(* Logix 5000 project; controller SMD34E2_EDS_AOI_Sample_RSLogix_V31 vendor 1 type 14 code 92 rev 31.11; software revision 31.00 *)

TASK MainTask (continuous, watchdog 500 ms) : MainProgram
TASK SMD34E2_follower_circular (task) : SMD34E2_follower_circular

MODULES
   Local : vendor 1 type 14 code 92 (ICP 0, rev 31.11)
      EN2TR : vendor 1 type 12 code 200 (ICP 2, Ethernet 192.168.0.5, rev 10.1)
         AMCI_SMD34E2 : vendor 10 type 12 code 28 (Ethernet 192.168.0.50, rev 1.6, StandardDataDriven RPI 8 ms)
END_MODULES

ADD_ON_INSTRUCTION AMCI_SMD34E2_Absolute_Move   (* revision 5.0, vendor AMCI, ExecuteEnableInFalse *)
// Revision note:
// Version 5.0 added the (hidden) ability to program the motor current and unlatched the error bit if the rung goes false.
VAR_INPUT
   Axis_Status_Bits : INT; {required}
   Type_0_for_standard_1_for_indexed : BOOL;
   Target_Position : DINT; {required}
   Programmed_Speed : DINT; {required}
   Acceleration : INT; {required}
   Deceleration : INT; {required}
   motor_current : INT;
   Jerk : INT;
END_VAR
VAR_IN_OUT
   AMCI_SMD34E2_output_data : _000A:SMD34E2_788832CB:O:0; {required}
END_VAR
VAR_OUTPUT
   EN : BOOL; {access Read Only, visible}
   ER : BOOL; {access Read Only, visible}
END_VAR
VAR
   Upper_Result_X_1000 : DINT;
   command_data_block : INT[10];
        [1]   // Command Bits LSW
        [3]   // Lower Target Position
        [0]   // Command Bits MSW
        [5]   // Lower Programmed Speed
        [2]   // Upper Target Position
        [4]   // Upper Programmed Speed
END_VAR

ROUTINE EnableInFalse   (* ladder *)
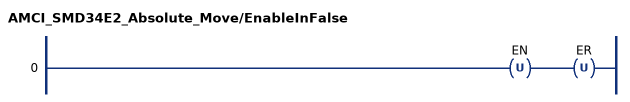
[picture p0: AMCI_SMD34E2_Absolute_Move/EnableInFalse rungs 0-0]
   0: OTU(EN)OTU(ER);
END_ROUTINE

ROUTINE Logic   (* ladder *)
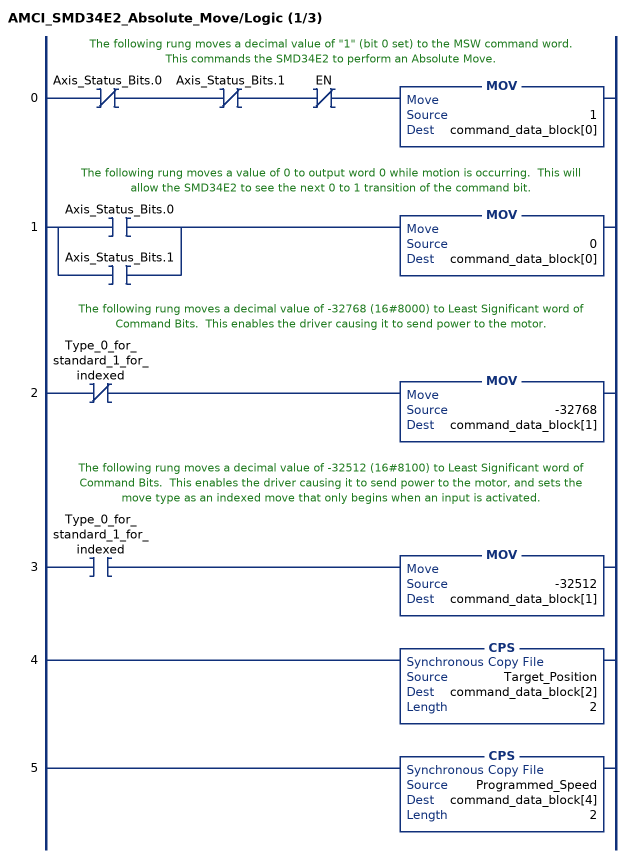
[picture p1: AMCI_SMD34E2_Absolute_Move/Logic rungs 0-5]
   // The following rung moves a decimal value of "1" (bit 0 set) to the MSW command word.  This commands the SMD34E2 to perform an Absolute Move.
   0: XIO(Axis_Status_Bits.0)XIO(Axis_Status_Bits.1)XIO(EN)MOV(1,command_data_block[0]);
   // The following rung moves a value of 0 to output word 0 while motion is occurring.  This will allow the SMD34E2 to see the next 0 to 1 transition of the command bit.
   1: [XIC(Axis_Status_Bits.0) ,XIC(Axis_Status_Bits.1) ]MOV(0,command_data_block[0]);
   // The following rung moves a decimal value of -32768 (16#8000) to Least Significant word of Command Bits.  This enables the driver causing it to send power to the motor.
   2: XIO(Type_0_for_standard_1_for_indexed)MOV(-32768,command_data_block[1]);
   // The following rung moves a decimal value of -32512 (16#8100) to Least Significant word of Command Bits.  This enables the driver causing it to send power to the motor, and sets the move type as an indexed move that only begins when an input is activated.
   3: XIC(Type_0_for_standard_1_for_indexed)MOV(-32512,command_data_block[1]);
   4: CPS(Target_Position,command_data_block[2],2);
   5: CPS(Programmed_Speed,command_data_block[4],2);
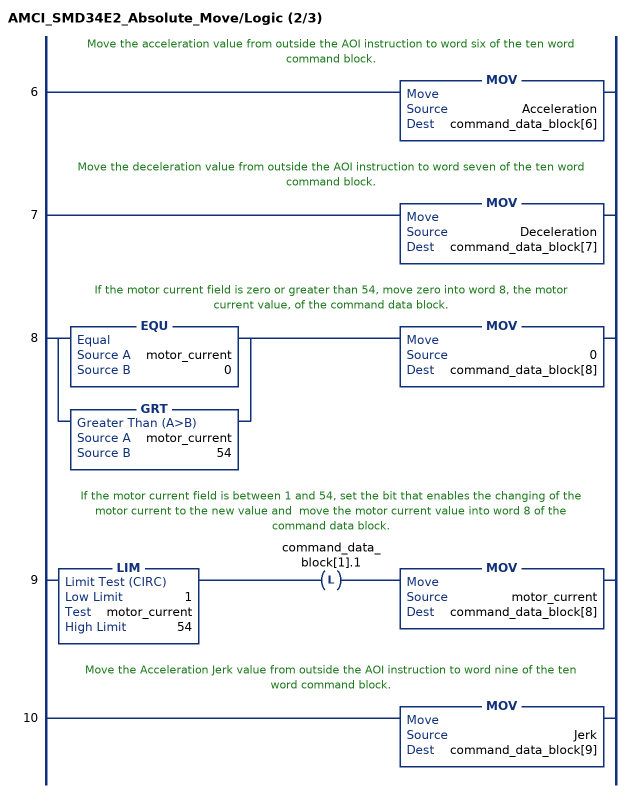
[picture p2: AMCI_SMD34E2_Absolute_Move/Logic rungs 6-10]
   // Move the acceleration value from outside the AOI instruction to word six of the ten word command block.
   6: MOV(Acceleration,command_data_block[6]);
   // Move the deceleration value from outside the AOI instruction to word seven of the ten word command block.
   7: MOV(Deceleration,command_data_block[7]);
   // If the motor current field is zero or greater than 54, move zero into word 8, the motor current value, of the command data block.
   8: [EQU(motor_current,0) ,GRT(motor_current,54) ]MOV(0,command_data_block[8]);
   // If the motor current field is between 1 and 54, set the bit that enables the changing of the motor current to the new value and  move the motor current value into word 8 of the command data block.
   9: LIM(1,motor_current,54)OTL(command_data_block[1].1)MOV(motor_current,command_data_block[8]);
   // Move the Acceleration Jerk value from outside the AOI instruction to word nine of the ten word command block.
   10: MOV(Jerk,command_data_block[9]);
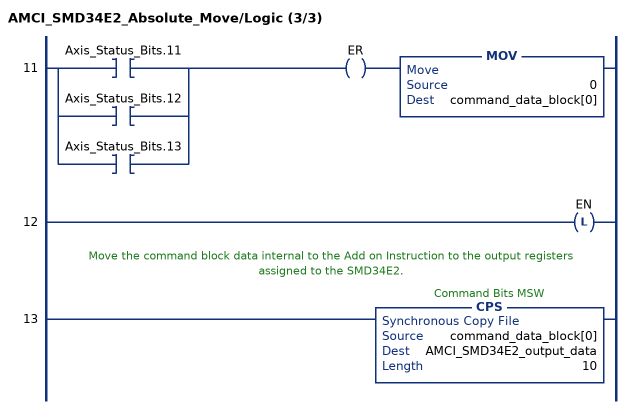
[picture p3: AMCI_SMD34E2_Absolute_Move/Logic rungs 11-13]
   11: [XIC(Axis_Status_Bits.11) ,XIC(Axis_Status_Bits.12) ,XIC(Axis_Status_Bits.13) ]OTE(ER)MOV(0,command_data_block[0]);
   12: OTL(EN);
   // Move the command block data internal to the Add on Instruction to the output registers assigned to the SMD34E2.
   13: CPS(command_data_block[0],AMCI_SMD34E2_output_data,10);
END_ROUTINE
END_ADD_ON_INSTRUCTION

ADD_ON_INSTRUCTION AMCI_SMD34E2_Axis_Follower_Circular   (* revision 5.0, vendor AMCI, ExecuteEnableInFalse *)
// Revision note:
// Version 5.0  unlatches the error bit if the rung goes false.  Also modified the Axis Follower commands to by default use the jog CCW command and have an option of the jog CW command.  (The status bits of the jog CCW update faster and the jog CW has smoother motion.)
// Help:
// 2/2017: V0 is the initial release
// 7/2017: V1 added enable and error bits.
// 5/2019: V2 added unlatching the error bit when the rung goes false and the ability to select between normal (jog CCW) and continuous follower (jog CW)
VAR_OUTPUT
   EN : BOOL; {visible}
END_VAR
VAR_INPUT
   Axis_Status_Bits : INT; {required}
   _0_for_Normal_1_for_Continuous : BOOL;
   _0_follow_motor_1_follow_encoder : BOOL;
   Follower_Position : REAL; {required}
   Follower_Velocity : REAL; {required}
   Acceleration : INT; {required}
   Deceleration : INT; {required}
   Proportional_Coefficient : INT; {required}
   Conversion_Constant : REAL; {required}
   Position_Unwind : INT; {required}
END_VAR
VAR_OUTPUT
   Axis_Follower_occurring : BOOL; {visible}
END_VAR
VAR_IN_OUT
   AMCI_SMD34E2_output_data : _000A:SMD34E2_788832CB:O:0; {required}
END_VAR
VAR_OUTPUT
   ER : BOOL; {visible}
END_VAR
VAR
   command_data_block : INT[10];
        [1]   // Command Bits LSW
        [3]   // Lower Target Position
        [5]   // Lower Programmed Speed
        [0]   // Command Bits MSW
        [2]   // Upper Target Position
        [4]   // Upper Programmed Speed
   axis_follower_position : DINT;
   axis_follower_velocity : DINT;
END_VAR

ROUTINE EnableInFalse   (* ladder *)
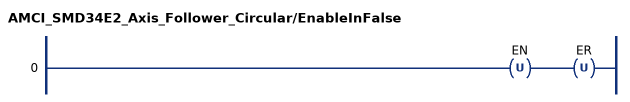
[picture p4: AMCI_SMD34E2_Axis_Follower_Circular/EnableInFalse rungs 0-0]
   0: OTU(EN)OTU(ER);
END_ROUTINE

ROUTINE Logic   (* ladder *)
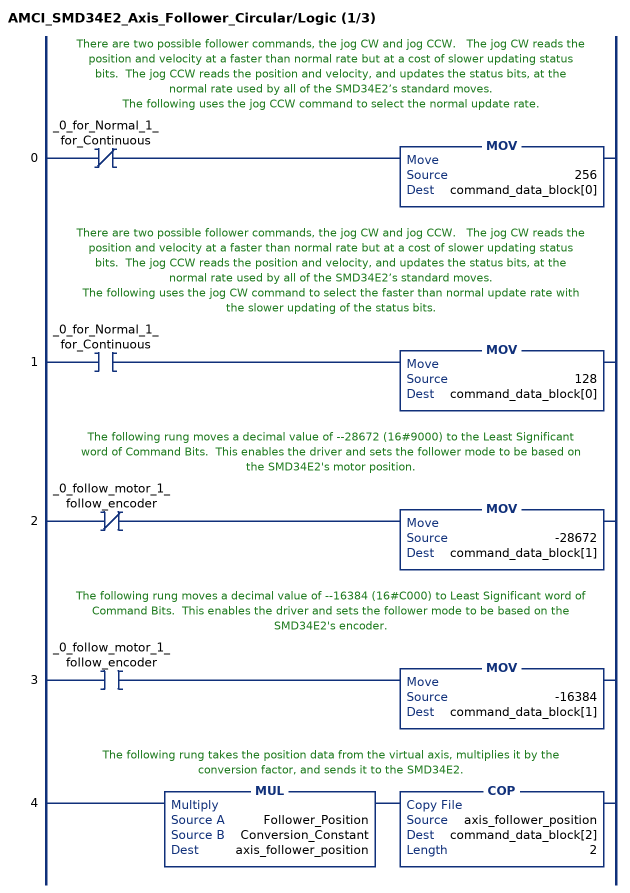
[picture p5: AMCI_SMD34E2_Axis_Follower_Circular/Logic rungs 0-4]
   // There are two possible follower commands, the jog CW and jog CCW.   The jog CW reads the position and velocity at a faster than normal rate but at a cost of slower updating status bits.  The jog CCW reads the position and velocity, and updates the status bits, at the normal rate used by all of the SMD34E2’s standard moves.
   // The following uses the jog CCW command to select the normal update rate.
   0: XIO(_0_for_Normal_1_for_Continuous)MOV(256,command_data_block[0]);
   // There are two possible follower commands, the jog CW and jog CCW.   The jog CW reads the position and velocity at a faster than normal rate but at a cost of slower updating status bits.  The jog CCW reads the position and velocity, and updates the status bits, at the normal rate used by all of the SMD34E2’s standard moves.
   // The following uses the jog CW command to select the faster than normal update rate with the slower updating of the status bits.
   1: XIC(_0_for_Normal_1_for_Continuous)MOV(128,command_data_block[0]);
   // The following rung moves a decimal value of --28672 (16#9000) to the Least Significant word of Command Bits.  This enables the driver and sets the follower mode to be based on the SMD34E2's motor position.
   2: XIO(_0_follow_motor_1_follow_encoder)MOV(-28672,command_data_block[1]);
   // The following rung moves a decimal value of --16384 (16#C000) to Least Significant word of Command Bits.  This enables the driver and sets the follower mode to be based on the SMD34E2's encoder.
   3: XIC(_0_follow_motor_1_follow_encoder)MOV(-16384,command_data_block[1]);
   // The following rung takes the position data from the virtual axis, multiplies it by the conversion factor, and sends it to the SMD34E2.
   4: MUL(Follower_Position,Conversion_Constant,axis_follower_position)COP(axis_follower_position,command_data_block[2],2);
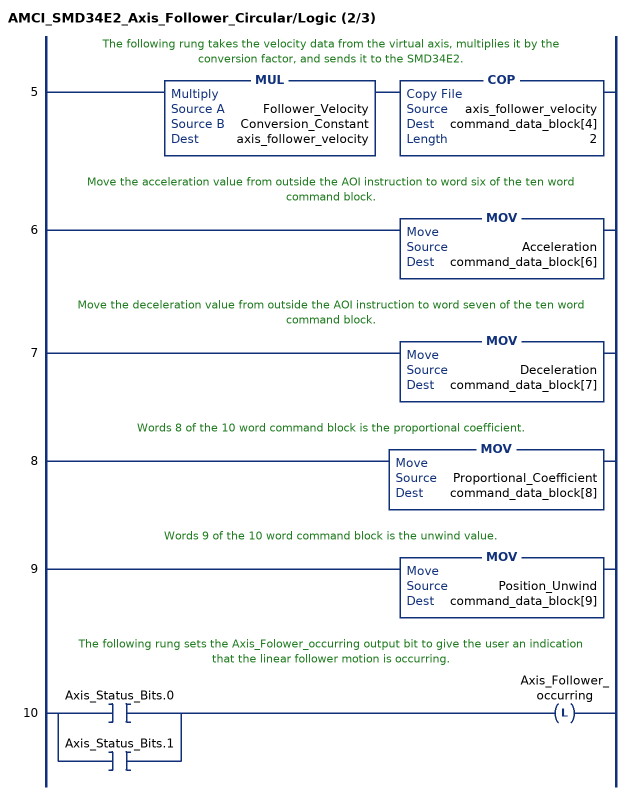
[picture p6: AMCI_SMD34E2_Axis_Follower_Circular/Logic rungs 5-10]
   // The following rung takes the velocity data from the virtual axis, multiplies it by the conversion factor, and sends it to the SMD34E2.
   5: MUL(Follower_Velocity,Conversion_Constant,axis_follower_velocity)COP(axis_follower_velocity,command_data_block[4],2);
   // Move the acceleration value from outside the AOI instruction to word six of the ten word command block.
   6: MOV(Acceleration,command_data_block[6]);
   // Move the deceleration value from outside the AOI instruction to word seven of the ten word command block.
   7: MOV(Deceleration,command_data_block[7]);
   // Words 8 of the 10 word command block is the proportional coefficient.
   8: MOV(Proportional_Coefficient,command_data_block[8]);
   // Words 9 of the 10 word command block is the unwind value.
   9: MOV(Position_Unwind,command_data_block[9]);
   // The following rung sets the Axis_Folower_occurring output bit to give the user an indication that the linear follower motion is occurring.
   10: [XIC(Axis_Status_Bits.0) ,XIC(Axis_Status_Bits.1) ]OTL(Axis_Follower_occurring);
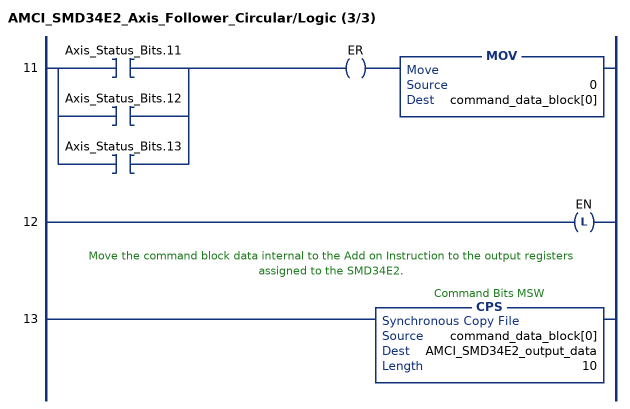
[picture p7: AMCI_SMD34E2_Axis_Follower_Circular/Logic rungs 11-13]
   11: [XIC(Axis_Status_Bits.11) ,XIC(Axis_Status_Bits.12) ,XIC(Axis_Status_Bits.13) ]OTE(ER)MOV(0,command_data_block[0]);
   12: OTL(EN);
   // Move the command block data internal to the Add on Instruction to the output registers assigned to the SMD34E2.
   13: CPS(command_data_block[0],AMCI_SMD34E2_output_data,10);
END_ROUTINE
END_ADD_ON_INSTRUCTION

ADD_ON_INSTRUCTION AMCI_SMD34E2_Axis_Follower_Linear   (* revision 5.0, vendor AMCI, ExecuteEnableInFalse *)
// Revision note:
// Version 5.0  unlatches the error bit if the rung goes false.  Also modified the Axis Follower commands to by default use the jog CCW command and have an option of the jog CW command.  (The status bits of the jog CCW update faster and the jog CW has smoother motion.)
// Help:
// 2/2017: V0 is the initial release
// 7/2017: V1 added enable and error bits.
// 5/2019: V2 added unlatching the error bit when the rung goes false and the ability to select between normal (jog CCW) and continuous follower (jog CW)
VAR_OUTPUT
   EN : BOOL; {visible}
END_VAR
VAR_INPUT
   Axis_Status_Bits : INT; {required}
   _0_for_Normal_1_for_Continuous : BOOL;
   _0_follow_motor_1_follow_encoder : BOOL;
   Follower_Position : REAL; {required}
   Follower_Velocity : REAL; {required}
   Acceleration : INT; {required}
   Deceleration : INT; {required}
   Proportional_Coefficient : INT; {required}
   Network_delay : INT; {required}
END_VAR
VAR_OUTPUT
   Axis_Follower_occurring : BOOL; {visible}
END_VAR
VAR_IN_OUT
   AMCI_SMD34E2_output_data : _000A:SMD34E2_788832CB:O:0; {required}
END_VAR
VAR_OUTPUT
   ER : BOOL; {visible}
END_VAR
VAR
   command_data_block : INT[10];
        [1]   // Command Bits LSW
        [3]   // Lower Target Position
        [5]   // Lower Programmed Speed
        [0]   // Command Bits MSW
        [2]   // Upper Target Position
        [4]   // Upper Programmed Speed
   axis_follower_position : DINT;
   axis_follower_velocity : DINT;
END_VAR

ROUTINE EnableInFalse   (* ladder *)
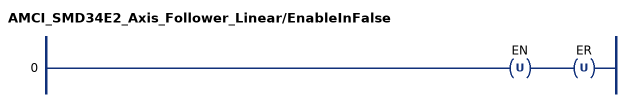
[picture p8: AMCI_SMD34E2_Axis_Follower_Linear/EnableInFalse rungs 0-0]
   0: OTU(EN)OTU(ER);
END_ROUTINE

ROUTINE Logic   (* ladder *)
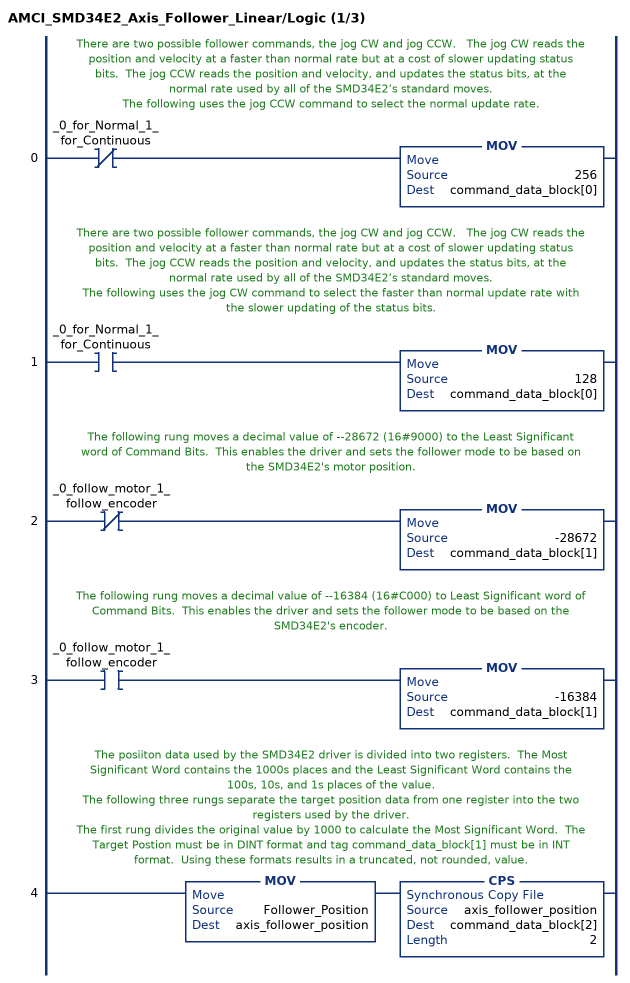
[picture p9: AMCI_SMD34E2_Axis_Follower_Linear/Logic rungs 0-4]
   // There are two possible follower commands, the jog CW and jog CCW.   The jog CW reads the position and velocity at a faster than normal rate but at a cost of slower updating status bits.  The jog CCW reads the position and velocity, and updates the status bits, at the normal rate used by all of the SMD34E2’s standard moves.
   // The following uses the jog CCW command to select the normal update rate.
   0: XIO(_0_for_Normal_1_for_Continuous)MOV(256,command_data_block[0]);
   // There are two possible follower commands, the jog CW and jog CCW.   The jog CW reads the position and velocity at a faster than normal rate but at a cost of slower updating status bits.  The jog CCW reads the position and velocity, and updates the status bits, at the normal rate used by all of the SMD34E2’s standard moves.
   // The following uses the jog CW command to select the faster than normal update rate with the slower updating of the status bits.
   1: XIC(_0_for_Normal_1_for_Continuous)MOV(128,command_data_block[0]);
   // The following rung moves a decimal value of --28672 (16#9000) to the Least Significant word of Command Bits.  This enables the driver and sets the follower mode to be based on the SMD34E2's motor position.
   2: XIO(_0_follow_motor_1_follow_encoder)MOV(-28672,command_data_block[1]);
   // The following rung moves a decimal value of --16384 (16#C000) to Least Significant word of Command Bits.  This enables the driver and sets the follower mode to be based on the SMD34E2's encoder.
   3: XIC(_0_follow_motor_1_follow_encoder)MOV(-16384,command_data_block[1]);
   // The posiiton data used by the SMD34E2 driver is divided into two registers.  The Most Significant Word contains the 1000s places and the Least Significant Word contains the 100s, 10s, and 1s places of the value.
   // The following three rungs separate the target position data from one register into the two registers used by the driver.
   // The first rung divides the original value by 1000 to calculate the Most Significant Word.  The Target Postion must be in DINT format and tag command_data_block[1] must be in INT format.  Using these formats results in a truncated, not rounded, value.
   4: MOV(Follower_Position,axis_follower_position)CPS(axis_follower_position,command_data_block[2],2);
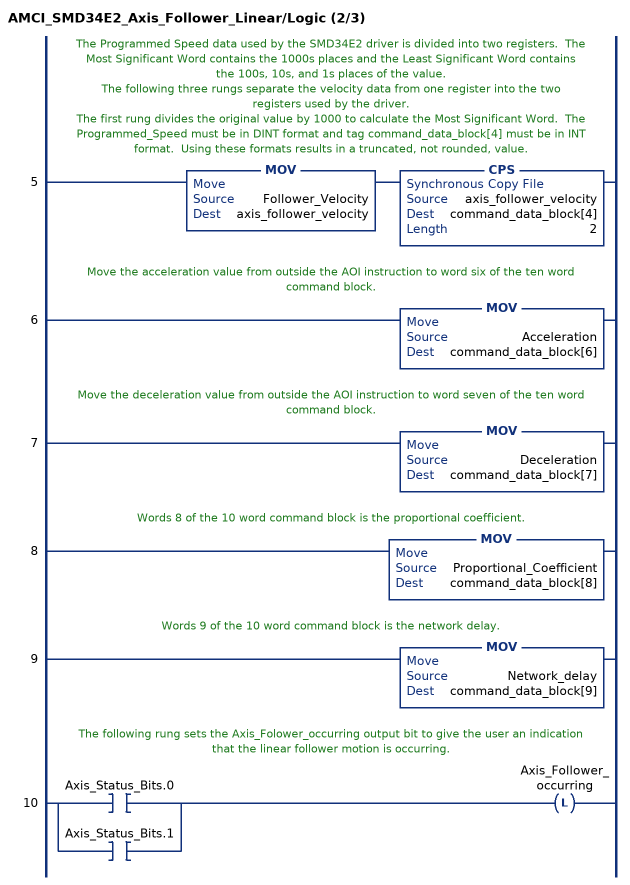
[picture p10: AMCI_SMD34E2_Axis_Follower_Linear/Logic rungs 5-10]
   // The Programmed Speed data used by the SMD34E2 driver is divided into two registers.  The Most Significant Word contains the 1000s places and the Least Significant Word contains the 100s, 10s, and 1s places of the value.
   // The following three rungs separate the velocity data from one register into the two registers used by the driver.
   // The first rung divides the original value by 1000 to calculate the Most Significant Word.  The Programmed_Speed must be in DINT format and tag command_data_block[4] must be in INT format.  Using these formats results in a truncated, not rounded, value.
   5: MOV(Follower_Velocity,axis_follower_velocity)CPS(axis_follower_velocity,command_data_block[4],2);
   // Move the acceleration value from outside the AOI instruction to word six of the ten word command block.
   6: MOV(Acceleration,command_data_block[6]);
   // Move the deceleration value from outside the AOI instruction to word seven of the ten word command block.
   7: MOV(Deceleration,command_data_block[7]);
   // Words 8 of the 10 word command block is the proportional coefficient.
   8: MOV(Proportional_Coefficient,command_data_block[8]);
   // Words 9 of the 10 word command block is the network delay.
   9: MOV(Network_delay,command_data_block[9]);
   // The following rung sets the Axis_Folower_occurring output bit to give the user an indication that the linear follower motion is occurring.
   10: [XIC(Axis_Status_Bits.0) ,XIC(Axis_Status_Bits.1) ]OTL(Axis_Follower_occurring);
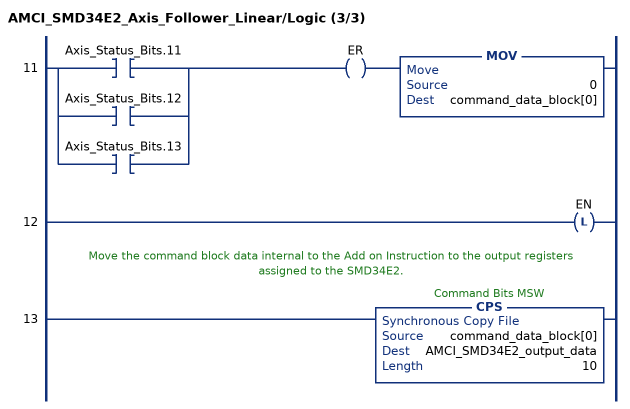
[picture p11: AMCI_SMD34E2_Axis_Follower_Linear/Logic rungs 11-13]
   11: [XIC(Axis_Status_Bits.11) ,XIC(Axis_Status_Bits.12) ,XIC(Axis_Status_Bits.13) ]OTE(ER)MOV(0,command_data_block[0]);
   12: OTL(EN);
   // Move the command block data internal to the Add on Instruction to the output registers assigned to the SMD34E2.
   13: CPS(command_data_block[0],AMCI_SMD34E2_output_data,10);
END_ROUTINE
END_ADD_ON_INSTRUCTION

ADD_ON_INSTRUCTION AMCI_SMD34E2_Disable_Driver   (* revision 1.0, vendor AMCI *)
VAR_IN_OUT
   AMCI_SMD34E2_output_data : _000A:SMD34E2_788832CB:O:0; {required}
END_VAR
VAR
   command_data_block : INT[10];
        [1]   // Command Bits LSW
        [5]   // Lower Programmed Speed
        [2]   // Upper Target Position
        [4]   // Upper Programmed Speed
        [3]   // Lower Target Position
        [0]   // Command Bits MSW
END_VAR

ROUTINE Logic   (* ladder *)
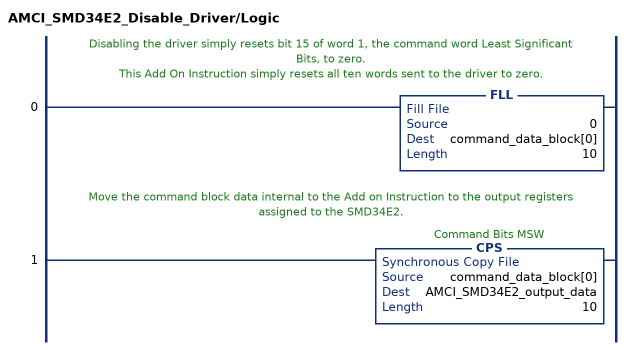
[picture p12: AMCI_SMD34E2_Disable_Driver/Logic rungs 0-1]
   // Disabling the driver simply resets bit 15 of word 1, the command word Least Significant Bits, to zero.
   // This Add On Instruction simply resets all ten words sent to the driver to zero.
   0: FLL(0,command_data_block[0],10);
   // Move the command block data internal to the Add on Instruction to the output registers assigned to the SMD34E2.
   1: CPS(command_data_block[0],AMCI_SMD34E2_output_data,10);
END_ROUTINE
END_ADD_ON_INSTRUCTION

ADD_ON_INSTRUCTION AMCI_SMD34E2_Enable_Driver   (* revision 1.0, vendor AMCI *)
VAR_IN_OUT
   AMCI_SMD34E2_output_data : _000A:SMD34E2_788832CB:O:0; {required}
END_VAR
VAR
   command_data_block : INT[10];
        [1]   // Command Bits LSW
        [3]   // Lower Target Position
        [5]   // Lower Programmed Speed
        [0]   // Command Bits MSW
        [2]   // Upper Target Position
        [4]   // Upper Programmed Speed
END_VAR

ROUTINE Logic   (* ladder *)
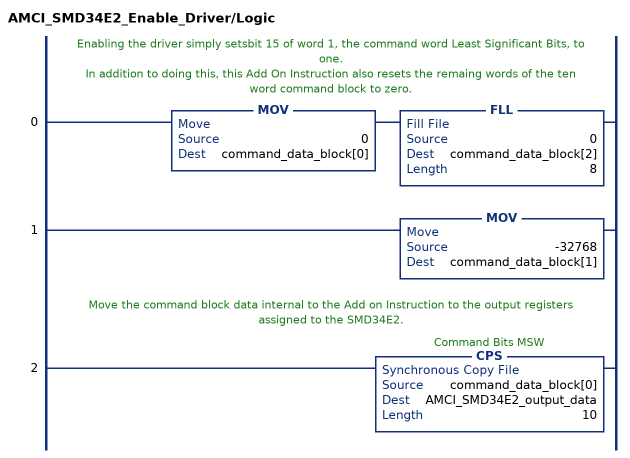
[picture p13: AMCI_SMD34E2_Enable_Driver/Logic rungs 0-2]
   // Enabling the driver simply setsbit 15 of word 1, the command word Least Significant Bits, to one.
   // In addition to doing this, this Add On Instruction also resets the remaing words of the ten word command block to zero.
   0: MOV(0,command_data_block[0])FLL(0,command_data_block[2],8);
   1: MOV(-32768,command_data_block[1]);
   // Move the command block data internal to the Add on Instruction to the output registers assigned to the SMD34E2.
   2: CPS(command_data_block[0],AMCI_SMD34E2_output_data,10);
END_ROUTINE
END_ADD_ON_INSTRUCTION

ADD_ON_INSTRUCTION AMCI_SMD34E2_Hold   (* revision 1.0, vendor AMCI *)
VAR_IN_OUT
   AMCI_SMD34E2_output_data : _000A:SMD34E2_788832CB:O:0; {required}
END_VAR
VAR
   command_data_block : INT[10];
        [1]   // Command Bits LSW
        [3]   // Lower Target Position
        [5]   // Lower Programmed Speed
        [0]   // Command Bits MSW
        [2]   // Upper Target Position
        [4]   // Upper Programmed Speed
END_VAR

ROUTINE Logic   (* ladder *)
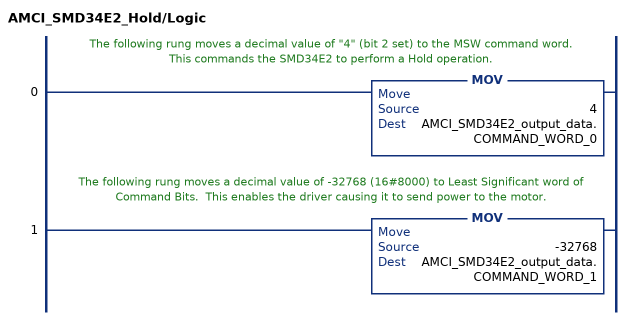
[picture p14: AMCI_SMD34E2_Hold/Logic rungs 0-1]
   // The following rung moves a decimal value of "4" (bit 2 set) to the MSW command word.  This commands the SMD34E2 to perform a Hold operation.
   0: MOV(4,AMCI_SMD34E2_output_data.COMMAND_WORD_0);
   // The following rung moves a decimal value of -32768 (16#8000) to Least Significant word of Command Bits.  This enables the driver causing it to send power to the motor.
   1: MOV(-32768,AMCI_SMD34E2_output_data.COMMAND_WORD_1);
END_ROUTINE
END_ADD_ON_INSTRUCTION

ADD_ON_INSTRUCTION AMCI_SMD34E2_Home_CCW   (* revision 5.0, vendor AMCI, ExecuteEnableInFalse *)
// Revision note:
// Version 5.0 added the (hidden) ability to program the motor current and unlatched the error bit if the rung goes false.
VAR_INPUT
   Axis_Status_Bits : INT; {required}
   Type_0_for_standard_1_for_indexed : BOOL;
   Programmed_Speed : DINT; {required}
   Acceleration : INT; {required}
   Deceleration : INT; {required}
   motor_current : INT;
   Jerk : INT;
END_VAR
VAR_IN_OUT
   AMCI_SMD34E2_output_data : _000A:SMD34E2_788832CB:O:0; {required}
END_VAR
VAR_OUTPUT
   EN : BOOL; {visible}
   ER : BOOL; {visible}
END_VAR
VAR
   Upper_Result_X_1000 : DINT;
   command_data_block : INT[10];
        [5]   // Lower Programmed Speed
        [1]   // Command Bits LSW
        [0]   // Command Bits MSW
        [3]   // Lower Target Position
        [2]   // Upper Target Position
        [4]   // Upper Programmed Speed
END_VAR

ROUTINE EnableInFalse   (* ladder *)
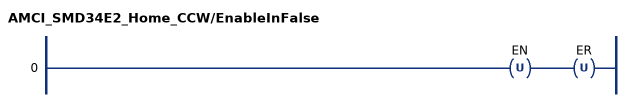
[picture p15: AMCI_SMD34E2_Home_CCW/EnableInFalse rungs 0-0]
   0: OTU(EN)OTU(ER);
END_ROUTINE

ROUTINE Logic   (* ladder *)
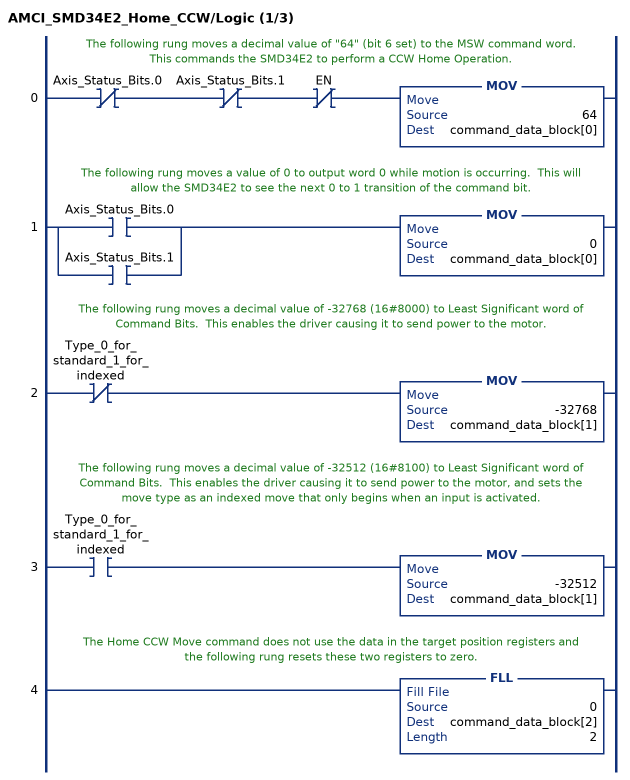
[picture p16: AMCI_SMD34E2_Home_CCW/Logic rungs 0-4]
   // The following rung moves a decimal value of "64" (bit 6 set) to the MSW command word.  This commands the SMD34E2 to perform a CCW Home Operation.
   0: XIO(Axis_Status_Bits.0)XIO(Axis_Status_Bits.1)XIO(EN)MOV(64,command_data_block[0]);
   // The following rung moves a value of 0 to output word 0 while motion is occurring.  This will allow the SMD34E2 to see the next 0 to 1 transition of the command bit.
   1: [XIC(Axis_Status_Bits.0) ,XIC(Axis_Status_Bits.1) ]MOV(0,command_data_block[0]);
   // The following rung moves a decimal value of -32768 (16#8000) to Least Significant word of Command Bits.  This enables the driver causing it to send power to the motor.
   2: XIO(Type_0_for_standard_1_for_indexed)MOV(-32768,command_data_block[1]);
   // The following rung moves a decimal value of -32512 (16#8100) to Least Significant word of Command Bits.  This enables the driver causing it to send power to the motor, and sets the move type as an indexed move that only begins when an input is activated.
   3: XIC(Type_0_for_standard_1_for_indexed)MOV(-32512,command_data_block[1]);
   // The Home CCW Move command does not use the data in the target position registers and the following rung resets these two registers to zero.
   4: FLL(0,command_data_block[2],2);
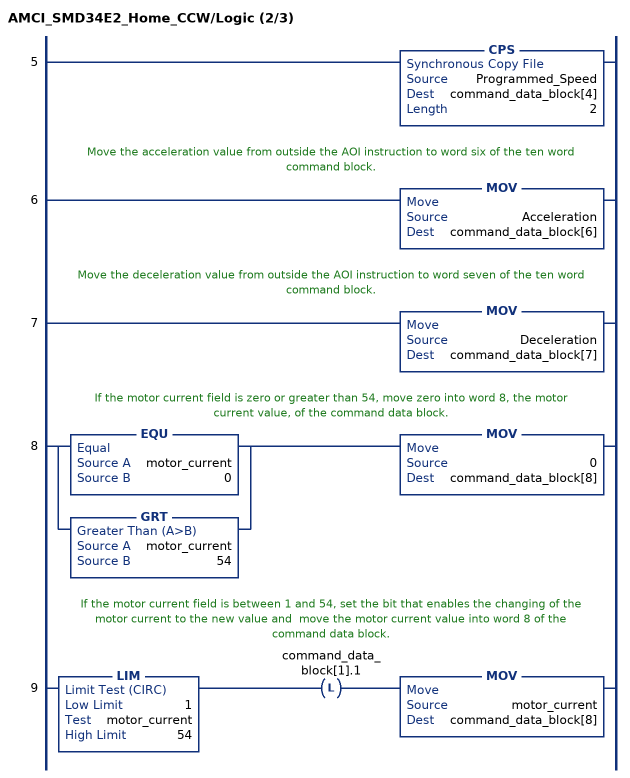
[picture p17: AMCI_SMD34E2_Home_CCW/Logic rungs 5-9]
   5: CPS(Programmed_Speed,command_data_block[4],2);
   // Move the acceleration value from outside the AOI instruction to word six of the ten word command block.
   6: MOV(Acceleration,command_data_block[6]);
   // Move the deceleration value from outside the AOI instruction to word seven of the ten word command block.
   7: MOV(Deceleration,command_data_block[7]);
   // If the motor current field is zero or greater than 54, move zero into word 8, the motor current value, of the command data block.
   8: [EQU(motor_current,0) ,GRT(motor_current,54) ]MOV(0,command_data_block[8]);
   // If the motor current field is between 1 and 54, set the bit that enables the changing of the motor current to the new value and  move the motor current value into word 8 of the command data block.
   9: LIM(1,motor_current,54)OTL(command_data_block[1].1)MOV(motor_current,command_data_block[8]);
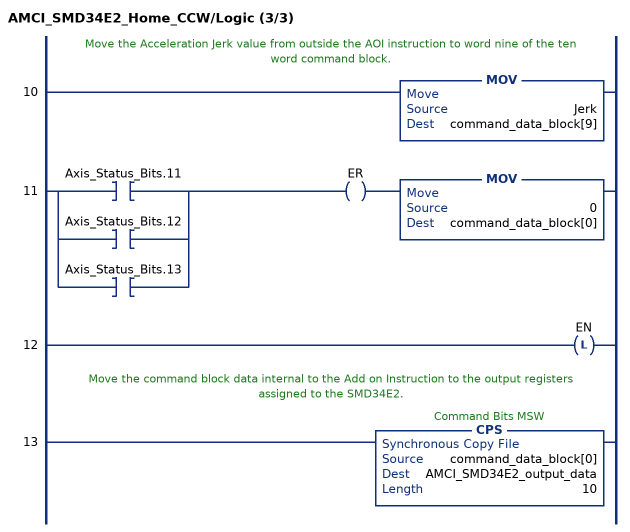
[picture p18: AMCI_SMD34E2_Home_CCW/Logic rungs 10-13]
   // Move the Acceleration Jerk value from outside the AOI instruction to word nine of the ten word command block.
   10: MOV(Jerk,command_data_block[9]);
   11: [XIC(Axis_Status_Bits.11) ,XIC(Axis_Status_Bits.12) ,XIC(Axis_Status_Bits.13) ]OTE(ER)MOV(0,command_data_block[0]);
   12: OTL(EN);
   // Move the command block data internal to the Add on Instruction to the output registers assigned to the SMD34E2.
   13: CPS(command_data_block[0],AMCI_SMD34E2_output_data,10);
END_ROUTINE
END_ADD_ON_INSTRUCTION
